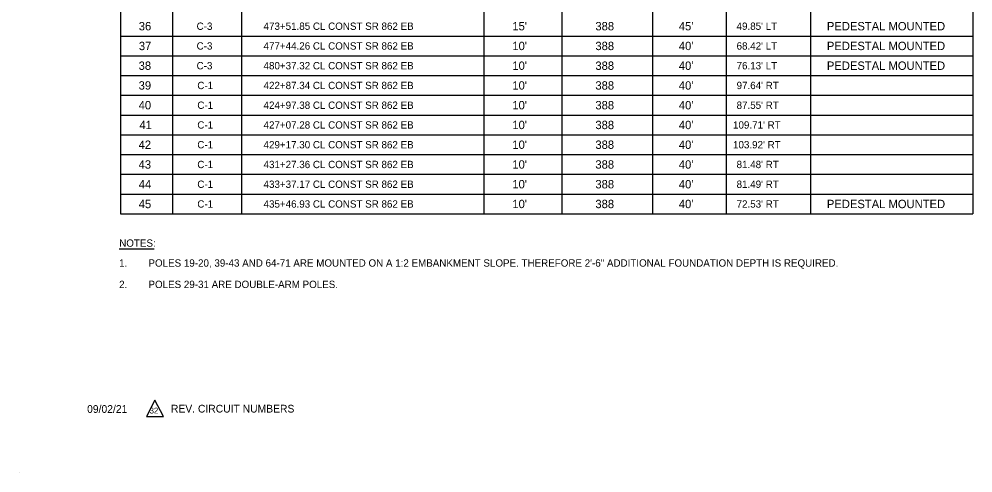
# Model space of a CAD drawing. Extents: x -818.1 to -802.4, y -2198.1 to -2187.9.
# Drawn here: x -818.09 to -810.11, y -2198.11 to -2194.32 of the extents above; entities that cross this region are included whole.
import ezdxf

# ---------------------------------------------------------------- set-up
doc = ezdxf.new("R2010")
doc.units = 0
for name, color, linetype in [('AdhocPoint_dp', 7, 'Continuous'), ('SumBoxBorder_dp', 7, 'Continuous'), ('SumBoxLines_dp', 7, 'Continuous'), ('SumBoxLinesMin_dp', 7, 'Continuous'), ('TextLabel', 7, 'Continuous'), ('TextNotes', 7, 'Continuous')]:
    doc.layers.add(name, color=color, linetype=linetype)

msp = doc.modelspace()

# ---------------------------------------------------------------- linework, layer by layer
at = {"layer": 'AdhocPoint_dp'}
msp.add_line((-818.0862, -2198.1071), (-818.0862, -2198.1071), dxfattribs=at)
at = {"layer": 'SumBoxBorder_dp'}
for p, q in [((-817.2394, -2187.8581), (-817.2394, -2195.9431)), ((-810.1144, -2187.8581), (-810.1144, -2195.9431)), ((-810.1144, -2187.8581), (-810.1144, -2195.9431)), ((-817.2394, -2195.9431), (-811.4719, -2195.9431)), ((-814.2019, -2195.9431), (-812.1769, -2195.9431)), ((-811.4719, -2195.9431), (-810.1144, -2195.9431))]:
    msp.add_line(p, q, dxfattribs=at)
at = {"layer": 'SumBoxLines_dp'}
for p, q in [((-816.8044, -2188.1881), (-816.8044, -2195.9431)), ((-816.8044, -2188.1881), (-816.8044, -2195.9431)), ((-816.2269, -2188.1881), (-816.2269, -2195.9431)), ((-814.2019, -2188.1881), (-814.2019, -2195.9431)), ((-813.5494, -2188.1881), (-813.5494, -2195.9431)), ((-813.5494, -2188.1881), (-813.5494, -2195.9431)), ((-812.7919, -2188.1881), (-812.7919, -2195.9431)), ((-812.7919, -2188.1881), (-812.7919, -2195.9431)), ((-812.1769, -2188.1881), (-812.1769, -2195.9431)), ((-811.4719, -2188.1881), (-811.4719, -2195.6131)), ((-811.4719, -2188.1881), (-811.4719, -2195.9431)), ((-814.2019, -2194.1281), (-814.2019, -2195.6131)), ((-816.2269, -2194.4581), (-816.2269, -2195.9431)), ((-812.1769, -2194.4581), (-812.1769, -2195.6131)), ((-814.2019, -2195.7781), (-814.2019, -2195.9431)), ((-812.1769, -2195.7781), (-812.1769, -2195.9431)), ((-811.4719, -2195.7781), (-811.4719, -2195.9431))]:
    msp.add_line(p, q, dxfattribs=at)
at = {"layer": 'SumBoxLinesMin_dp'}
for p, q in [((-817.2394, -2194.4581), (-816.8044, -2194.4581)), ((-817.2394, -2194.4581), (-810.1144, -2194.4581)), ((-816.2269, -2194.4581), (-812.7919, -2194.4581)), ((-812.1769, -2194.4581), (-810.1144, -2194.4581)), ((-817.2394, -2194.6231), (-810.1144, -2194.6231)), ((-817.2394, -2194.6231), (-810.1144, -2194.6231)), ((-817.2394, -2194.7881), (-810.1144, -2194.7881)), ((-817.2394, -2194.7881), (-810.1144, -2194.7881)), ((-817.2394, -2194.9531), (-810.1144, -2194.9531)), ((-817.2394, -2194.9531), (-810.1144, -2194.9531)), ((-817.2394, -2195.1181), (-810.1144, -2195.1181)), ((-817.2394, -2195.1181), (-810.1144, -2195.1181)), ((-817.2394, -2195.2831), (-810.1144, -2195.2831)), ((-817.2394, -2195.2831), (-810.1144, -2195.2831)), ((-817.2394, -2195.4481), (-810.1144, -2195.4481)), ((-817.2394, -2195.4481), (-810.1144, -2195.4481)), ((-817.2394, -2195.6131), (-810.1144, -2195.6131)), ((-817.2394, -2195.6131), (-810.1144, -2195.6131)), ((-817.2394, -2195.7781), (-816.2269, -2195.7781)), ((-817.2394, -2195.7781), (-810.1144, -2195.7781)), ((-814.2019, -2195.7781), (-812.7919, -2195.7781)), ((-812.1769, -2195.7781), (-810.1144, -2195.7781)), ((-817.2394, -2195.9431), (-816.8044, -2195.9431))]:
    msp.add_line(p, q, dxfattribs=at)
at = {"layer": 'TextLabel'}
msp.add_line((-817.2493, -2196.2358), (-816.9574, -2196.2358), dxfattribs=at)
at = {"layer": 'TextNotes'}
msp.add_lwpolyline([(-816.9512, -2197.4983), (-817.0223, -2197.6351), (-816.8802, -2197.6351)], close=True, dxfattribs=at)

# ---------------------------------------------------------------- texts
at = {"layer": 'TextLabel'}
for s, height, p in [('36', 0.07, (-817.0858, -2194.4106)), ('C-3', 0.06125, (-816.6025, -2194.4063)), ('473+51.85 CL CONST SR 862 EB', 0.06125, (-816.0428, -2194.4063)), ("15'", 0.07, (-813.9636, -2194.4106)), ('388', 0.07, (-813.2696, -2194.4106)), ("45'", 0.07, (-812.5723, -2194.4106)), ("49.85' LT", 0.06125, (-812.0896, -2194.4063)), ('PEDESTAL MOUNTED', 0.07, (-811.3349, -2194.4106)), ('37', 0.07, (-817.0852, -2194.5756)), ('C-3', 0.06125, (-816.6025, -2194.5713)), ('477+44.26 CL CONST SR 862 EB', 0.06125, (-816.0428, -2194.5713)), ("10'", 0.07, (-813.9636, -2194.5756)), ('388', 0.07, (-813.2696, -2194.5756)), ("40'", 0.07, (-812.5723, -2194.5756)), ("68.42' LT", 0.06125, (-812.0896, -2194.5713)), ('PEDESTAL MOUNTED', 0.07, (-811.3349, -2194.5756)), ('38', 0.07, (-817.0869, -2194.7406)), ('C-3', 0.06125, (-816.6025, -2194.7363)), ('480+37.32 CL CONST SR 862 EB', 0.06125, (-816.0428, -2194.7363)), ("10'", 0.07, (-813.9636, -2194.7406)), ('388', 0.07, (-813.2696, -2194.7406)), ("40'", 0.07, (-812.5723, -2194.7406)), ("76.13' LT", 0.06125, (-812.0896, -2194.7363)), ('PEDESTAL MOUNTED', 0.07, (-811.3349, -2194.7406)), ('39', 0.07, (-817.0868, -2194.9056)), ('C-1', 0.06125, (-816.5965, -2194.9013)), ('422+87.34 CL CONST SR 862 EB', 0.06125, (-816.0428, -2194.9013)), ("10'", 0.07, (-813.9636, -2194.9056)), ('388', 0.07, (-813.2696, -2194.9056)), ("40'", 0.07, (-812.5723, -2194.9056)), ("97.64' RT", 0.06125, (-812.0896, -2194.9013)), ('40', 0.07, (-817.0866, -2195.0706)), ('C-1', 0.06125, (-816.5965, -2195.0663)), ('424+97.38 CL CONST SR 862 EB', 0.06125, (-816.0428, -2195.0663)), ("10'", 0.07, (-813.9636, -2195.0706)), ('388', 0.07, (-813.2696, -2195.0706)), ("40'", 0.07, (-812.5723, -2195.0706)), ("87.55' RT", 0.06125, (-812.0896, -2195.0663)), ('41', 0.07, (-817.0805, -2195.2356)), ('C-1', 0.06125, (-816.5965, -2195.2313)), ('427+07.28 CL CONST SR 862 EB', 0.06125, (-816.0428, -2195.2313)), ("10'", 0.07, (-813.9636, -2195.2356)), ('388', 0.07, (-813.2696, -2195.2356)), ("40'", 0.07, (-812.5723, -2195.2356)), ("109.71' RT", 0.06125, (-812.1193, -2195.2313)), ('42', 0.07, (-817.0872, -2195.4006)), ('C-1', 0.06125, (-816.5965, -2195.3963)), ('429+17.30 CL CONST SR 862 EB', 0.06125, (-816.0428, -2195.3963)), ("10'", 0.07, (-813.9636, -2195.4006)), ('388', 0.07, (-813.2696, -2195.4006)), ("40'", 0.07, (-812.5723, -2195.4006)), ("103.92' RT", 0.06125, (-812.1193, -2195.3963)), ('43', 0.07, (-817.0872, -2195.5656)), ('C-1', 0.06125, (-816.5965, -2195.5613)), ('431+27.36 CL CONST SR 862 EB', 0.06125, (-816.0428, -2195.5613)), ("10'", 0.07, (-813.9636, -2195.5656)), ('388', 0.07, (-813.2696, -2195.5656)), ("40'", 0.07, (-812.5723, -2195.5656)), ("81.48' RT", 0.06125, (-812.0896, -2195.5613)), ('44', 0.07, (-817.0858, -2195.7306)), ('C-1', 0.06125, (-816.5965, -2195.7263)), ('433+37.17 CL CONST SR 862 EB', 0.06125, (-816.0428, -2195.7263)), ("10'", 0.07, (-813.9636, -2195.7306)), ('388', 0.07, (-813.2696, -2195.7306)), ("40'", 0.07, (-812.5723, -2195.7306)), ("81.49' RT", 0.06125, (-812.0896, -2195.7263)), ('45', 0.07, (-817.0863, -2195.8956)), ("10'", 0.07, (-813.9636, -2195.8956)), ('388', 0.07, (-813.2696, -2195.8956)), ("40'", 0.07, (-812.5723, -2195.8956)), ('PEDESTAL MOUNTED', 0.07, (-811.3349, -2195.8956)), ('C-1', 0.06125, (-816.5965, -2195.8913)), ('435+46.93 CL CONST SR 862 EB', 0.06125, (-816.0428, -2195.8913)), ("72.53' RT", 0.06125, (-812.0896, -2195.8913)), ('NOTES:', 0.06125, (-817.2492, -2196.2179)), ('1.', 0.06125, (-817.2498, -2196.3843)), ('POLES 19-20, 39-43 AND 64-71 ARE MOUNTED ON A 1:2 EMBANKMENT SLOPE. THEREFORE 2\'-6" ADDITIONAL FOUNDATION DEPTH IS REQUIRED.', 0.06125, (-817.0048, -2196.3843)), ('2.', 0.06125, (-817.2498, -2196.5628)), ('POLES 29-31 ARE DOUBLE-ARM POLES.', 0.06125, (-817.0048, -2196.5628))]:
    msp.add_text(s, height=height, dxfattribs=at).set_placement(p)
for s, p in [('09/02/21', (-817.5176, -2197.6055)), ('REV. CIRCUIT NUMBERS', (-816.8169, -2197.6028))]:
    msp.add_text(s, height=0.06456, rotation=0, dxfattribs=at).set_placement(p)
at = {"layer": 'TextNotes'}
msp.add_text('32', height=0.04842, rotation=360, dxfattribs=at).set_placement((-816.995, -2197.6108))

doc.saveas('drawing.dxf')
